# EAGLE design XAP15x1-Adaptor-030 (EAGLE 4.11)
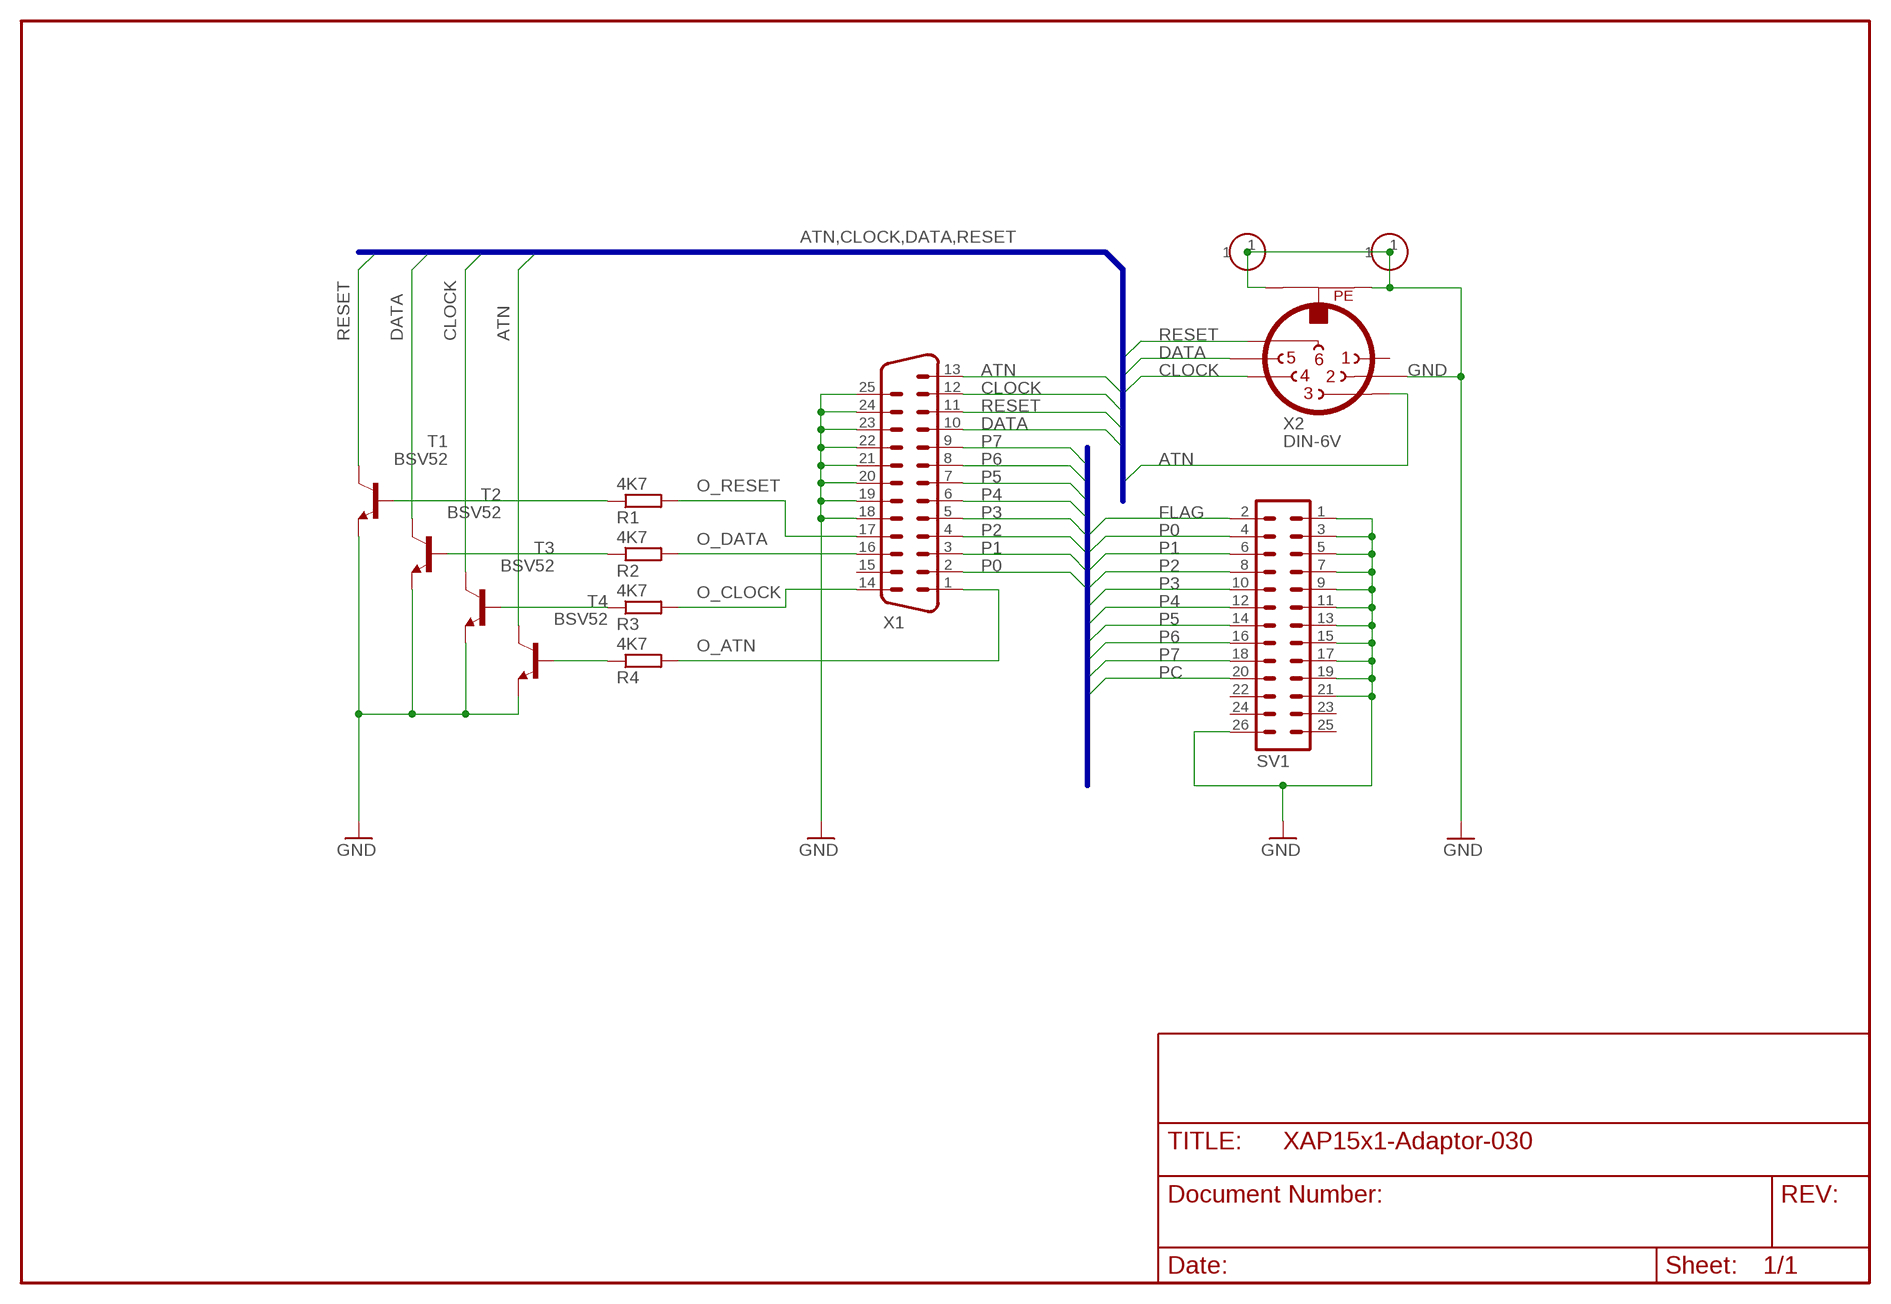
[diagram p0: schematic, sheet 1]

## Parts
R1  4K7  R-EU_R1206  [R1206]
R2  4K7  R-EU_R1206  [R1206]
R3  4K7  R-EU_R1206  [R1206]
R4  4K7  R-EU_R1206  [R1206]
SV1  ML26  [ML26]
T1  BSV52  BSV52LT1-NPN-SOT23-BEC  [SOT23-BEC]
T2  BSV52  BSV52LT1-NPN-SOT23-BEC  [SOT23-BEC]
T3  BSV52  BSV52LT1-NPN-SOT23-BEC  [SOT23-BEC]
T4  BSV52  BSV52LT1-NPN-SOT23-BEC  [SOT23-BEC]
U$1  HOLE-3MM  [HOLE-3MM]
U$2  HOLE-3MM  [HOLE-3MM]
X1  M25D  [M25D]
X2  DIN-6V  [DIN-6V]

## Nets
ATN: T4.C X1.13 X2.3
CLOCK: T3.C X1.12 X2.4
DATA: T2.C X1.10 X2.5
FLAG: SV1.2
GND: SV1.1 SV1.3 SV1.5 SV1.7 SV1.9 SV1.11 SV1.13 SV1.15 SV1.17 SV1.19 SV1.21 SV1.26 T1.E T2.E T3.E T4.E U$1.1 U$2.1 X1.18 X1.19 X1.20 X1.21 X1.22 X1.23 X1.24 X1.25 X2.2 X2.7 X2.8
N$1: R1.1 T1.B
N$2: R2.1 T2.B
N$3: R3.1 T3.B
N$4: R4.1 T4.B
O_ATN: R4.2 X1.1
O_CLOCK: R3.2 X1.14
O_DATA: R2.2 X1.16
O_RESET: R1.2 X1.17
P0: SV1.4 X1.2
P1: SV1.6 X1.3
P2: SV1.8 X1.4
P3: SV1.10 X1.5
P4: SV1.12 X1.6
P5: SV1.14 X1.7
P6: SV1.16 X1.8
P7: SV1.18 X1.9
PC: SV1.20
RESET: T1.C X1.11 X2.6
Unconnected: SV1.22 SV1.23 SV1.24 SV1.25 X1.15 X2.1

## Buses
FLAG,P[0..7],PC
ATN,CLOCK,DATA,RESET

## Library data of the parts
R1-R4 = rcl:R-EU_: RESISTOR, European symbol
SV1 = con-harting-ml:ML26: HARTING
T1-T4 = transistor:*-NPN-: NPN Transistror
U$1 U$2 = _OwnParts:HOLE-3MM
X1 = con-subd:M25: SUB-D
X2 = _OwnParts:DIN-6V

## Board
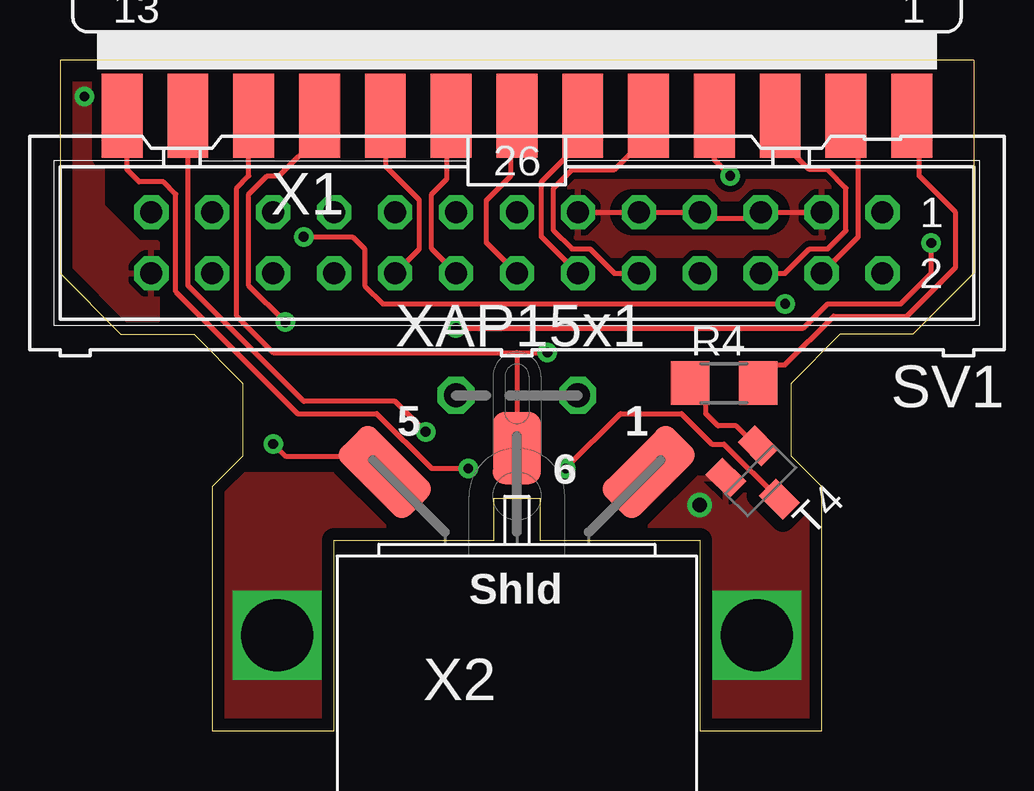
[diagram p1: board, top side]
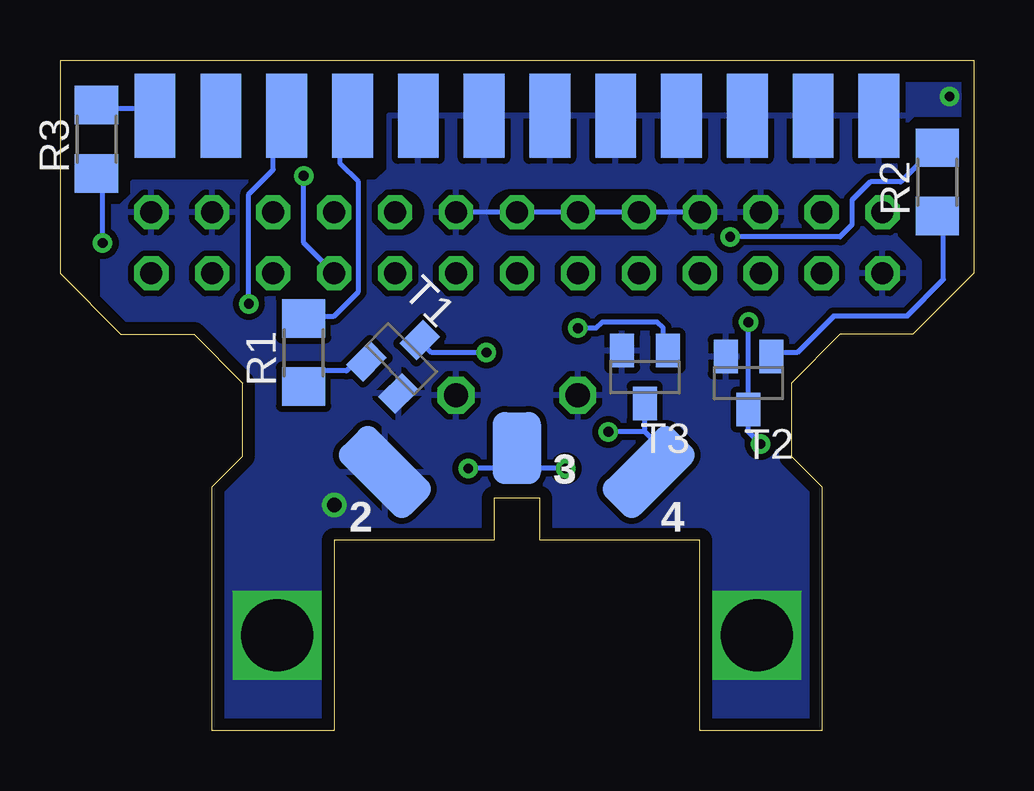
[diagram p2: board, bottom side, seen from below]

Size 38.1 x 27.94 mm. Coordinates in mm from the lower left corner, seen from the top.
Outline: 38.1,27.94 0,27.94 0,19.05 2.54,16.51 5.59,16.51 7.62,14.48 7.62,11.43 6.35,10.16 6.35,0 11.43,0 11.43,7.94 18.1,7.94 18.1,9.68 20,9.68 20,7.94 26.67,7.94 26.67,0 31.75,0 31.75,10.16 30.48,11.43 30.48,14.48 32.51,16.51 35.56,16.51 38.1,19.05 38.1,27.94
Copper layers (1*16): Top 0.035mm / dielectric 1.5mm / Bottom 0.035mm
Design rules "default": minimum track width 8mil, minimum drill 16mil, track to track 8mil, track to pad 8mil, pad to pad 8mil, via to via 8mil, smd to smd 8mil, copper to edge 20mil, drill to drill 8mil, minimum pad ring 10mil, minimum via ring 8mil, stop-mask expansion 4mil, vias tented up to drill 0mil, thermal gap 10mil
tRestrict: 3 lines
bRestrict: 3 lines

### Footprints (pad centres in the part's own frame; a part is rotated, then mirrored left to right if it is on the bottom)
R1206 = smd 1.6 x 1.803: 1 -1.422,0; 2 1.422,0
ML26 = drill 0.914 octagon: 1 -15.24,-1.27; 2 -15.24,1.27; 3 -12.7,-1.27; 4 -12.7,1.27; 5 -10.16,-1.27; 6 -10.16,1.27; 7 -7.62,-1.27; 8 -7.62,1.27; 9 -5.08,-1.27; 10 -5.08,1.27; 11 -2.54,-1.27; 12 -2.54,1.27; 13 0,-1.27; 14 0,1.27; 15 2.54,-1.27; 16 2.54,1.27; 17 5.08,-1.27; 18 5.08,1.27; 19 7.62,-1.27; 20 7.62,1.27; 21 10.16,-1.27; 22 10.16,1.27; 23 12.7,-1.27; 24 12.7,1.27; 25 15.24,-1.27; 26 15.24,1.27
SOT23-BEC = smd 1 x 1.4: B -0.95,-1.1; C 0,1.1; E 0.95,-1.1
HOLE-3MM = drill 3 pad 3.7 square: 1 0,0
M25D = smd 1.7 x 3.5: 1 16.459,-6.045; 2 13.716,-6.045; 3 10.973,-6.045; 4 8.23,-6.045; 5 5.486,-6.045; 6 2.743,-6.045; 7 0,-6.045; 8 -2.743,-6.045; 9 -5.486,-6.045; 10 -8.23,-6.045; 11 -10.973,-6.045; 12 -13.716,-6.045; 13 -16.459,-6.045 | smd 1.7 x 3.5 bottom: 14 15.088,-6.045; 15 12.344,-6.045; 16 9.601,-6.045; 17 6.858,-6.045; 18 4.115,-6.045; 19 1.372,-6.045; 20 -1.372,-6.045; 21 -4.115,-6.045; 22 -6.858,-6.045; 23 -9.601,-6.045; 24 -12.344,-6.045; 25 -15.088,-6.045
DIN-6V = smd 4 x 2 rotated 45: 1 5.5,9.5 | smd 4 x 2 rotated 225 bottom: 2 5.5,9.5 | smd 2 x 3 bottom: 3 0,10.5 | smd 4 x 2 rotated 135 bottom: 4 -5.5,9.5 | smd 4 x 2 rotated 135: 5 -5.5,9.5 | smd 2 x 3: 6 0,10.5 | drill 1.016 octagon: 7 2.54,12.7; 8 -2.54,12.7

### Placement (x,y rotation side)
R1  27.94,15.75 90 bottom
R2  1.52,22.86 90 bottom
R3  36.58,24.64 90 bottom
R4  27.69,14.48 0 top
SV1  19.05,20.32 180 top
T1  23.87,15.49 315 bottom
T2  9.4,14.48 180 bottom
T3  13.72,14.73 180 bottom
T4  29.21,10.41 225 top
U$1  29.05,3.97 0 top
U$2  9.05,3.97 0 top
X1  19.05,31.65 0 top
X2  19.05,1.27 0 top

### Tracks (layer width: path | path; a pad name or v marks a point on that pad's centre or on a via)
ATN  (via drill 0.41)
  Top 0.203: X1.13 2.79,25.65 2.79,23.37 3.3,22.86 4.32,22.86 4.83,22.35 4.83,18.29 9.91,13.21 13.21,13.21 15.49,10.92 v17.02,10.92 | T4.C 27.69,11.94 27.18,11.94 25.91,13.21 23.37,13.21 v21.08,10.92
  Bottom 0.203: 19.05,10.92 X2.3 | v17.02,10.92 19.05,10.92 | 19.05,10.92 v21.08,10.92
CLOCK  (via drill 0.41)
  Top 0.203: X1.12 5.33,18.54 10.16,13.72 13.97,13.72 v15.24,12.45
  Bottom 0.203: X2.4 13.55,10.83 12.95,11.43 12.95,11.68 13.71,12.44 13.71,12.45 | 13.71,12.45 T3.C | 13.71,12.45 v15.24,12.45
DATA  (via drill 0.41)
  Top 0.203: v8.89,11.94 9.4,11.43 12.7,11.43 13.36,10.77 X2.5 | X1.10 10.82,24.79 9.14,23.11 8.64,23.11 7.87,22.35 7.87,18.54 v9.4,17.02
  Bottom 0.203: v9.4,17.02 9.4,13.72 9.4,13.46 T2.C 9.4,12.45 v8.89,11.94
GND  (via drill 0.41, 0.61)
  Top 0.203: SV1.11 SV1.9 SV1.7 26.92,21.34 28.96,21.34 SV1.5 SV1.3
  Bottom 0.203: SV1.11 SV1.13 SV1.15 SV1.17 SV1.19
  other vias: 26.67,9.4 1.02,26.42
  pour Bottom (isolate 0.254): 0.51,26.92 0.51,25.65 2.54,25.65 2.79,25.4 3.3,25.4 3.3,20.57 2.29,19.56 2.29,16.76 2.54,16.51 5.59,16.51 7.62,14.48 7.62,11.43 6.35,10.16 6.35,0 11.43,0 11.43,7.87 26.67,7.87 26.67,0 31.75,0 31.75,10.16 30.48,11.43 30.48,14.48 32.51,16.51 35.56,16.51 36.32,17.27 36.32,21.84 35.56,21.84 35.05,22.35 35.05,22.86 24.89,22.86 24.38,23.37 24.38,25.65 3.56,25.65 3.56,26.92
  pour Top (isolate 0.254): 20.57,22.86 20.57,19.81 32.77,19.81 32.77,22.86
  pour Bottom (isolate 0.406, no thermals, hatched): 6.35,0 6.35,7.11 11.43,7.11 11.43,0
  pour Bottom (isolate 0.406, no thermals, hatched): 26.67,0 26.67,7.11 31.75,7.11 31.75,0
  pour Top (isolate 0.508): 6.35,10.16 6.35,0 11.43,0 11.43,7.87 26.67,7.87 26.67,0 31.75,0 31.75,10.16 31.24,10.67 6.86,10.67
  pour Top (isolate 0.406): 0,26.92 0,19.05 2.54,16.51 4.06,16.51 4.06,20.32 3.3,20.32 1.78,21.84 1.78,26.92
N$1
  Bottom 0.203: T1.B 25.58,15.57 26.16,14.99 27.94,14.99 27.94,14.22 R1.1
N$2
  Bottom 0.203: R2.1 1.37,21.44 1.27,21.34 1.27,18.8 2.79,17.27 5.84,17.27 7.37,15.75 8.38,15.75 8.31,15.68 T2.B
N$3  (via drill 0.41)
  Top 0.203: v16.51,16.76 30.99,16.76 32,17.78 35.05,17.78 36.32,19.05 v36.32,20.32
  Bottom 0.203: v36.32,20.32 36.32,22.61 36.68,22.61 R3.1 | T3.B 12.63,16.07 12.95,16.26 12.95,16.76 13.21,17.02 15.49,17.02 15.75,16.76 v16.51,16.76
N$4
  Top 0.203: T4.B 29.1,12.09 28.96,11.94 28.19,12.7 27.43,12.7 26.92,13.21 26.92,14.48 26.42,14.48 26.41,14.48 R4.1
O_ATN
  Top 0.203: X1.1 35.35,25.61 35.81,25.4 35.81,23.11 37.34,21.59 37.34,19.3 35.31,17.27 32.26,17.27 30.23,15.24 28.7,15.24 28.7,14.48 28.6,14.48 R4.2
O_CLOCK
  Bottom 0.203: X1.14 34.14,25.55 34.29,25.91 36.58,25.91 R3.2
O_DATA  (via drill 0.41)
  Top 0.203: v30.23,17.78 13.46,17.78 12.7,18.54 12.7,20.07 12.19,20.57 v10.16,20.57
  Bottom 0.203: X1.16 28.65,24.94 29.21,24.38 29.21,23.37 30.23,22.35 v30.23,17.78 | R2.2 1.52,24.38 3.05,22.86 4.32,22.86 5.08,22.1 5.08,21.08 5.59,20.57 v10.16,20.57
O_RESET
  Bottom 0.203: X1.17 25.86,25.36 26.42,25.4 26.42,23.62 25.65,22.86 25.65,18.29 26.67,17.27 27.69,17.27 R1.2
P0
  Top 0.203: SV1.4 33.27,20.57 33.27,25.65 X1.2 32.77,25.65
P1
  Top 0.203: SV1.6 30.23,19.05 31.24,20.07 32,20.07 32.77,20.83 32.77,22.61 32,23.37 31.24,23.37 29.97,24.64 29.97,25.15 30.02,25.32 X1.3
P2  (via drill 0.41)
  Top 0.203: X1.4 27.28,23.77 v27.94,23.11
  Bottom 0.203: v27.94,23.11 27.94,20.32 SV1.8
P3
  Top 0.203: X1.5 24.34,25.61 23.88,25.15 23.88,24.13 23.11,23.37 21.34,23.37 20.57,22.61 20.57,20.83 21.34,20.07 22.1,20.07 23.11,19.05 SV1.10
P4
  Top 0.203: X1.6 21.29,25.61 21.08,25.4 21.08,23.88 20.07,22.86 20.07,20.57 SV1.12
P5
  Top 0.203: X1.7 19.01,25.61 18.8,25.4 18.8,23.11 17.78,22.1 17.78,20.32 SV1.14
P6
  Top 0.203: SV1.16 15.49,20.07 15.49,22.35 16.13,22.99 16.13,25.43 X1.8
P7
  Top 0.203: X1.9 13.59,25.38 13.59,23.5 14.99,22.1 14.99,20.07 SV1.18
RESET  (via drill 0.41)
  Top 0.203: X1.11 8.29,25.4 7.87,25.4 7.87,23.11 7.37,22.61 7.37,17.27 8.89,15.75 19.05,15.75 | 19.05,15.75 X2.6 | 19.05,15.75 v20.32,15.75
  Bottom 0.203: T1.C 23.28,16 23.28,16.17 23.11,16.26 22.61,15.75 v20.32,15.75

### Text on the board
tNames: XAP15x1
